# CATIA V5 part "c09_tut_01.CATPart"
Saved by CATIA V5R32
Part number: Part1
Bounding box of the stored display mesh (mm): x -75 to 140, y -40 to 40, z 0 to 100
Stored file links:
  D:\PROJECTS\Project 2022\CATIA V5 6R 2022\Resources\Tutorial Files\c09_catia_v5_6r2022_tut\c09_tut_01.CATPart
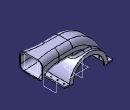
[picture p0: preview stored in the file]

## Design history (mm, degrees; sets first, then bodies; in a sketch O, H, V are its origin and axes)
Body1 (main body)
  Sketch1 on zx-plane, origin (0, 0, 0), H (-1, 0, 0), V (0, 0, 1)
    arc A1 centre (0, 0) radius 60 from (60, 0) to (-60, 0) ccw
    point P1 (-60, 0)
    line L1 (-60, 0) -> (60, 0)
    radius A1 = 60
    coincidence: P1 H
    horizontal: L1 H
  Pad1: profile Sketch1, direction (0, 1, 0), length 40, mirrored extent
  Sketch2 on zx-plane, origin (0, 0, 0), H (-1, 0, 0), V (0, 0, 1)
    point P1 (-82, 100)
    line L1 (-82, 100) -> (-40, 100)
    arc A1 centre (-40, 0) radius 100 from (-40, 100) to (60, 0) cw
    point P3 (-40, 0)
    point P4 (60, 0)
    reference projected line E1 (-60, 0) -> (60, 0) from edge [face of Pad1 from Sketch1.L1 | end face of Pad1]
    reference projected arc E3 centre (0, 0) radius 60 from (60, 0) to (-60, 0) ccw from edge [face of Pad1 from Sketch1.A1 | end face of Pad1]
    radius A1 = 100
    distance P1 V = 82
    horizontal: L1 H
    tangency: A1 L1, A1 E3
    coincidence: P3 E1, E1 P4
  Plane1: type Normal, Curve Sketch2, RefPoint Sketch2.P1, Ratio 0
  Sketch3 on Plane1, origin (82, 0, 0), H (0, 1, 0), V (0, 0, 1)
    line L1 (-29, 100) -> (29, 100)
    line L2 (29, 100) -> (29, 58)
    line L3 (29, 58) -> (-29, 58)
    line L4 (-29, 58) -> (-29, 100)
    reference projected point E1 (0, 100) from Sketch2.P1
    length L1 = 58
    distance L1 L3 = 42
    distance V L4 = 29
    horizontal: L1 H, L3 H
    vertical: L2 V, L4 V
    coincidence: L1 E1
  Rib1: profile Sketch3, centre curve Sketch2
  Plane2: type Offset, RefPlane face of Rib1, Offset 58, reversed
  Sketch4 on Plane2, origin (140, 0, 0), H (0, -1, 0), V (0, 0, 1)
    line L1 (36.5, 100) -> (-36.5, 100)
    line L2 (-36.5, 100) -> (-36.5, 47)
    line L3 (-36.5, 47) -> (36.5, 47)
    line L4 (36.5, 47) -> (36.5, 100)
    length L1 = 73
    length L2 = 53
    distance L2 V = 36.5
    distance L1 H = 100
    horizontal: L1 H, L3 H
    vertical: L2 V, L4 V
  Loft1: solid, Sections (Sketch4; {boundary Boundary {extract ExtractElem face of Rib1}}), EndFace face of Rib1
  Fillet1: radius 15, on edge [face of Loft1 | face of Rib1]; edge [face of Rib1 | face of Loft1]; edge [face of Loft1 | face of Loft1] (x2)
  Fillet2: radius 5, on edge [face of Pad1 from Sketch1.A1 | face of Fillet1]
  Shell1: ExtOffset 0, Face (face of Loft1; face of Rib1), IntOffset 2.5
  Sketch5 on end face of Pad1, origin (0, 40, 0), H (-1, 0, 0), V (0, 0, 1)
    arc A1 centre (0, 0) radius 49 from (49, 0) to (-49, 0) ccw
    reference projected arc E1 centre (0, 0) radius 60 from (60, 0) to (-60, 0) ccw from edge [face of Pad1 from Sketch1.A1 | end face of Pad1]
    axis line L1 (-49, 0) -> (49, 0)
    point P1 (-49, 0)
    radius A1 = 49
    concentricity: A1 E1
    coincidence: P1 H
    horizontal: L1 H
  Pocket1: profile Sketch5, direction (0, -1, 0), up to zx-plane
  Sketch6 on start face of Pad1, origin (0, -40, 0), H (1, 0, 0), V (0, 0, 1)
    arc A1 centre (0, 0) radius 15 from (15, 0) to (-15, 0) ccw
    axis line L1 (-15, 0) -> (15, 0)
    point P1 (-15, 0)
    radius A1 = 15
    coincidence: P1 H
    horizontal: L1 H
  Pocket2: profile Sketch6, direction (0, 1, 0), through (limit type 6)
  Sketch7 on face of Rib1, origin (0, 0, 0), H (1, 0, 0), V (0, -1, 0)
    line L1 (-75, 40) -> (-60, 40)
    line L2 (-60, -40) -> (-75, -40)
    line L3 (-75, -40) -> (-75, 40)
    reference projected line E1 (60, -40) -> (-60, -40) from edge [face of Rib1 | end face of Pad1]
    reference projected line E2 (60, 40) -> (-60, 40) from edge [start face of Pad1 | face of Rib1]
    reference projected point E3 (-60, -14) from vertex [face of Rib1 | face of Rib1 | face of Fillet1 | face of Pad1 from Sketch1.A1]
    length L1 = 15
    distance L3 E3 = 15
    horizontal: L1 H, L2 H
    vertical: L3 V
    coincidence: L2 E1, L1 E2
  Pad2: profile Sketch7, direction (0, 0, 1), length 4
  Mirror1: of Pad2, about yz-plane
  Sketch8 on face of Mirror1, origin (71.9019, 34.9362, 4), H (1, 0, 0), V (0, 1, 0)
    point P1 (-4.4019, -4.9362)
    reference projected line E1 (3.0981, -74.9362) -> (3.0981, 5.0638) from edge [face of Mirror1 | face of Mirror1]
    reference projected line E2 (3.0981, 5.0638) -> (-12.0354, 5.0638) from edge [face of Mirror1 | face of Mirror1]
    distance E1 P1 = 7.5
    distance E2 P1 = 10
  Hole1: placed by Sketch8, at (67.5, 30, 4) direction (0, 0, -1), diameter 4, through (limit type 6)
  RectPattern1: of Hole1, direction 1 instances 4, spacing 20, along edge [face of Mirror1 | face of Mirror1] reversed, direction 2 instances 3, spacing 135, along edge [face of Mirror1 | face of Mirror1] reversed
  Plane3: type Offset, RefPlane yz-plane, Offset 82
